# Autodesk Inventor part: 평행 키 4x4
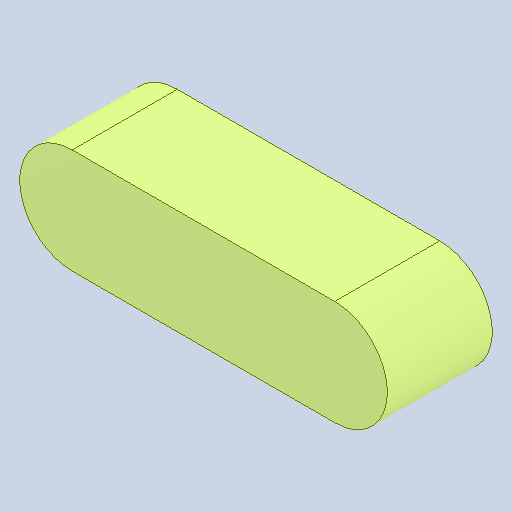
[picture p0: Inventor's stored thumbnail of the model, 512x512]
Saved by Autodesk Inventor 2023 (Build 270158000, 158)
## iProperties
Created: 2025-04
Part Number: 평행 키 4x4
Material: 강철, 연강
Document SubType Name: Modeling
Designer: ADMIN_PC
Density: 7.86 g/cm^3
Appearance: 기본값
Author: jhkim
Revision Number: 1
Sending System: Autodesk Inventor 2026
Preprocessor: ST-DEVELOPER v20.1
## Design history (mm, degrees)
feature "솔리드1"
node "솔리드2"
